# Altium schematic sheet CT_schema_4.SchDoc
size 205 x 258 mm
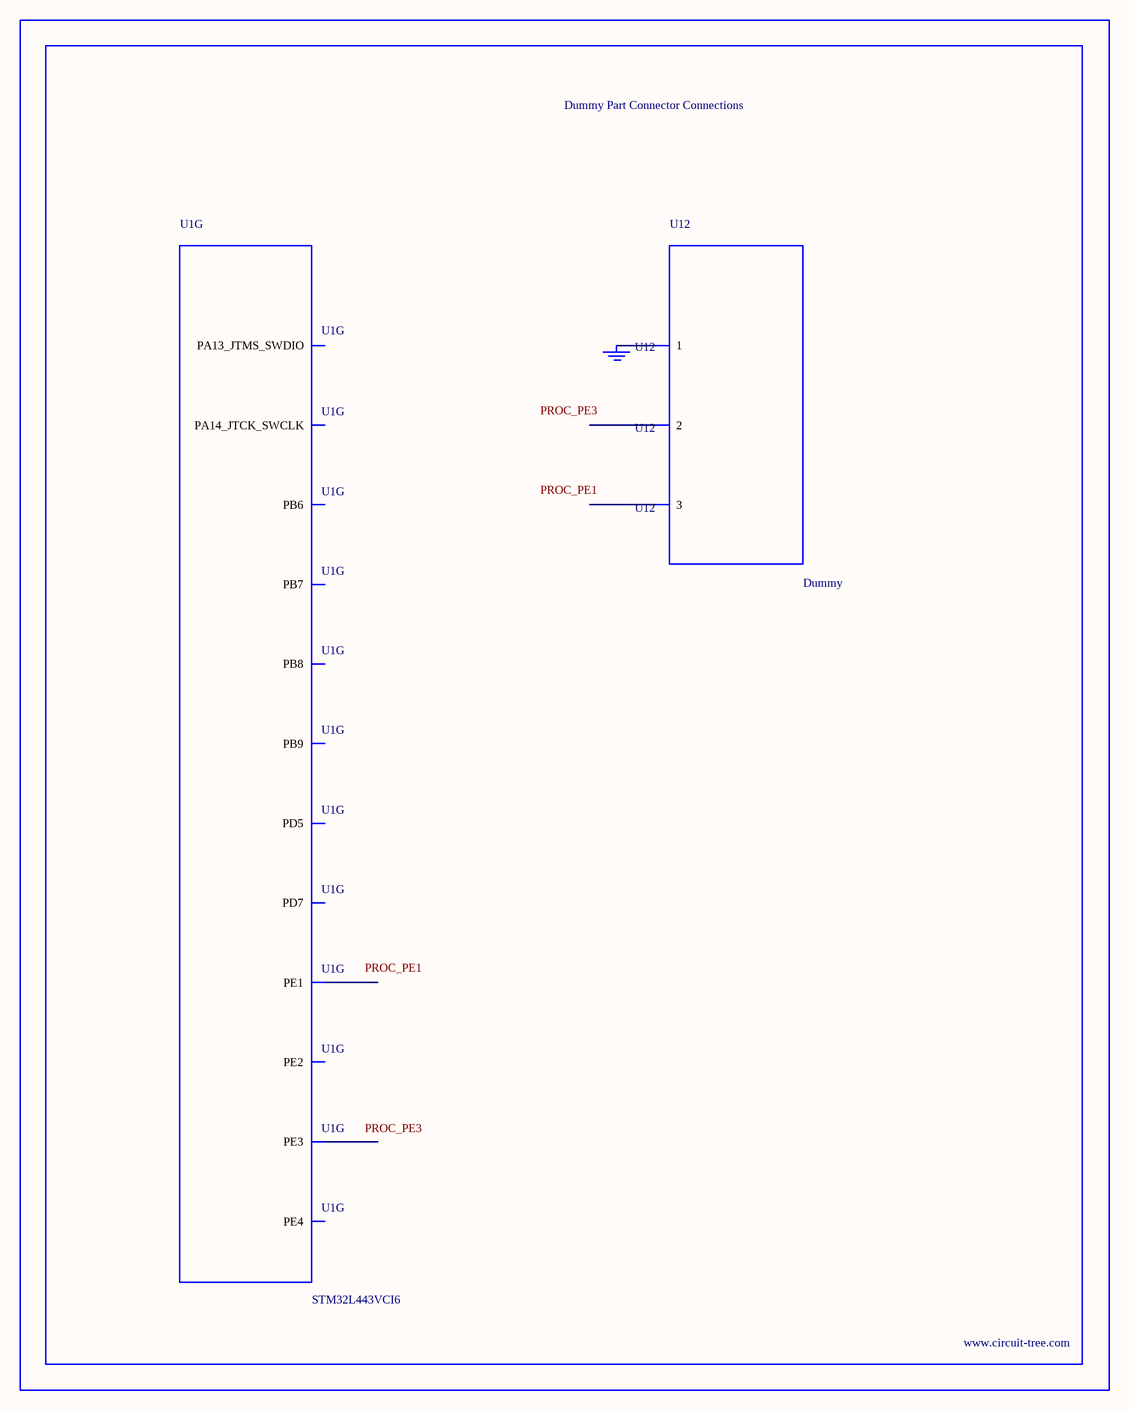
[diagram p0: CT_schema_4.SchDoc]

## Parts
BORDER3  (no value)
GND_INSTANCE_3_0  (no value)
U1  STM32L443VCI6  [UFBGA100]  (part G of 7)
U12  Dummy  [DUMMY_PACKAGE_104]

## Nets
NetGND_INSTANCE_3_0_0: GND_INSTANCE_3_0.0(GND) U12.1

Not connected (* = marked no-connect by the designer): U1 A1(PE3) A2(PE1) A3(PB8) A5(PD7) A6(PD5) A10(PA14_JTCK_SWCLK) A11(PA13_JTMS_SWDIO) B1(PE4) B2(PE2) B3(PB9) B4(PB7) B5(PB6); U12 2 3

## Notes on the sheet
- Labels drawn without touching a wire or pin: PROC_PE1, PROC_PE3

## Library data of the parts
BORDER3 = BORDER_PAGE3
GND_INSTANCE_3_0 = GND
